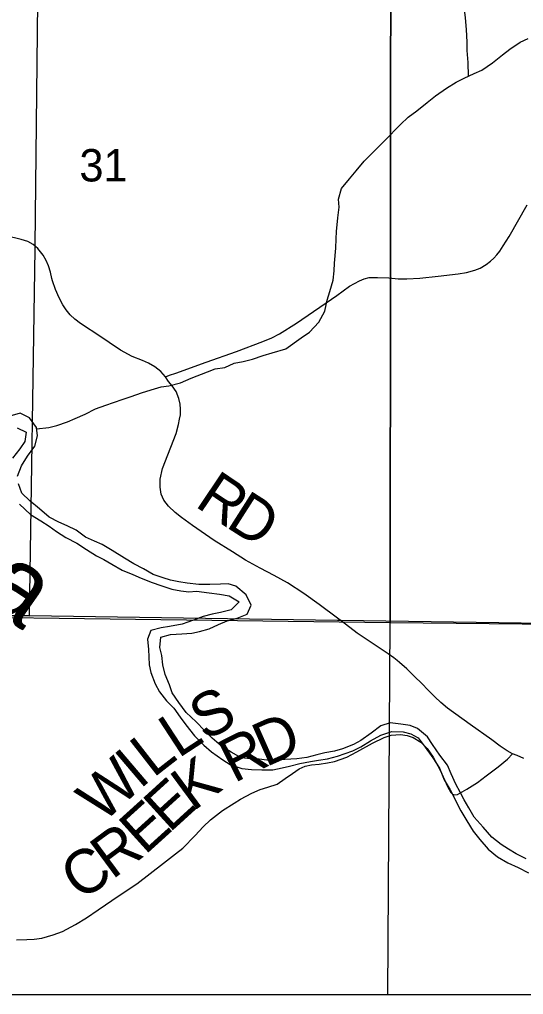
# Model space of a CAD drawing. Extents: x 0 to 191, y 0 to 55.
# Drawn here: x 184.796 to 185.447, y 47.92 to 49.18 of the extents above; entities that cross this region are included whole.
import ezdxf

# ---------------------------------------------------------------- set-up
doc = ezdxf.new("R2010")
doc.units = 0
for name, color, linetype in [('GM_X_Corporation', 7, 'Continuous'), ('GM_X_County_Road', 7, 'Continuous'), ('GM_X_County_Road_Text', 7, 'Continuous'), ('GM_X_Minor_River', 7, 'Continuous'), ('GM_X_Minor_River_Text', 7, 'Continuous'), ('GM_X_Section_Text', 7, 'Continuous'), ('GM_X_Township_Road', 7, 'Continuous')]:
    doc.layers.add(name, color=color, linetype=linetype)

msp = doc.modelspace()

# ---------------------------------------------------------------- linework, layer by layer
at = {"layer": 'GM_X_Corporation'}
for points in [[(184.1701, 53.923), (184.1701, 47.9197), (186.2932, 47.9197), (186.2941, 48.012), (186.2991, 48.3871), (186.4921, 48.3828), (187.098, 48.377), (187.7625, 48.3707), (187.7657, 48.3707), (188.3304, 48.3653), (188.401, 48.3646), (188.9117, 48.3542), (189.3607, 48.345), (189.6849, 48.3383), (190.1514, 48.3336), (190.3574, 48.3286), (190.3641, 48.8031), (190.3751, 50.4761)], [(184.1701, 53.923), (184.1701, 49.9388), (184.171, 49.9388), (184.1826, 49.9387), (184.1847, 49.9387), (184.3733, 49.937), (184.3701, 49.6407), (184.3701, 49.6374), (184.3608, 48.4162), (184.8085, 48.4088), (184.8161, 48.8829), (184.8161, 48.8869), (184.8319, 50.3441), (184.8319, 50.3472), (184.8438, 50.7018)], [(190.3751, 50.4761), (190.3641, 48.8031), (190.3574, 48.3286), (190.1514, 48.3336), (189.6849, 48.3383), (189.3607, 48.345), (188.9117, 48.3542), (188.401, 48.3646), (188.3304, 48.3653), (187.7657, 48.3707), (187.7625, 48.3707), (187.098, 48.377), (186.4921, 48.3828), (186.2991, 48.3871), (186.1484, 48.3893), (186.1442, 48.3893), (185.2112, 48.4029), (185.207, 48.403), (184.8085, 48.4088), (184.8161, 48.8829), (184.8161, 48.8869), (184.8319, 50.3441), (184.8319, 50.3472), (184.8438, 50.7018)]]:
    msp.add_lwpolyline(points, dxfattribs=at)
for points in [[(184.3647, 49.4297), (185.276, 49.4114), (185.2748, 48.3999), (184.3526, 48.412), (184.3573, 48.9248)], [(185.276, 49.4114), (186.3119, 49.3947), (186.3, 48.3895), (185.2748, 48.3999)], [(184.3521, 47.9197), (185.2718, 47.9197), (185.2748, 48.3999), (184.3526, 48.412), (184.3521, 47.9349)], [(184.357, 47.9197), (186.2932, 47.9197), (186.2941, 48.012), (186.2991, 48.3871), (186.1484, 48.3893), (186.1442, 48.3893), (185.2112, 48.4029), (185.207, 48.403), (184.8085, 48.4088), (184.3608, 48.4162)]]:
    msp.add_lwpolyline(points, close=True, dxfattribs=at)
at = {"layer": 'GM_X_County_Road'}
for points in [[(184.8383, 48.8419), (184.8374, 48.8447), (184.8356, 48.8529), (184.833, 48.8614), (184.8302, 48.868), (184.8265, 48.8749), (184.8194, 48.8836), (184.8163, 48.8864), (184.8136, 48.8889), (184.8067, 48.8928), (184.7978, 48.8952), (184.7783, 48.9001)], [(185.2839, 48.3514), (185.2798, 48.3548), (185.2723, 48.36), (185.2543, 48.3719), (185.2323, 48.3867), (185.2114, 48.4024), (185.2067, 48.4059), (185.1833, 48.4238), (185.1633, 48.438), (185.1423, 48.4517), (185.1252, 48.4613), (185.1071, 48.4704), (185.0881, 48.481), (185.0712, 48.4915), (185.0476, 48.5064), (185.0194, 48.5257), (185.0053, 48.5359), (184.9971, 48.5426), (184.9883, 48.5505), (184.9825, 48.5583), (184.979, 48.5663), (184.9777, 48.5753), (184.9777, 48.5856), (184.9807, 48.5995), (184.9981, 48.6446), (185.0014, 48.6563), (185.0028, 48.6632), (185.004, 48.6688), (185.004, 48.6762), (185.0035, 48.6827), (185.0017, 48.6898), (184.9981, 48.6987), (184.9929, 48.7062), (184.9883, 48.712), (184.9843, 48.7179), (184.9783, 48.7246), (184.9709, 48.7309), (184.9624, 48.7355), (184.9547, 48.7388), (184.9414, 48.7443), (184.9263, 48.7525), (184.9115, 48.7624), (184.9009, 48.7697), (184.8746, 48.7867), (184.8671, 48.7923), (184.8613, 48.7978), (184.856, 48.8045), (184.8517, 48.8109), (184.8468, 48.8201), (184.8421, 48.8308), (184.8383, 48.8419)], [(185.4331, 48.2306), (185.4261, 48.2345), (185.4171, 48.2406), (185.4065, 48.2488), (185.3786, 48.2687), (185.3491, 48.2898), (185.3406, 48.2968), (185.3328, 48.3043), (185.324, 48.3131), (185.3158, 48.3214), (185.3063, 48.3305), (185.2964, 48.3404), (185.2871, 48.3488), (185.2839, 48.3514)], [(184.7918, 47.9903), (184.8054, 47.9906), (184.8145, 47.9914), (184.8244, 47.9923), (184.8392, 47.9967), (184.8514, 48.0012), (184.8683, 48.0102), (184.8824, 48.0189), (184.8973, 48.029), (184.9247, 48.0475), (184.9474, 48.0626), (184.982, 48.0893), (184.9976, 48.1013), (185.0071, 48.1089), (185.023, 48.1253), (185.0331, 48.1362), (185.0428, 48.1452), (185.058, 48.1576), (185.0734, 48.167), (185.0816, 48.1721), (185.0961, 48.18), (185.1071, 48.1846), (185.1169, 48.1877), (185.129, 48.1917), (185.1391, 48.1986), (185.1486, 48.2051), (185.1575, 48.2111), (185.1651, 48.2148), (185.1732, 48.2164), (185.1831, 48.2172), (185.1938, 48.2189), (185.2032, 48.2208), (185.2188, 48.2264), (185.2318, 48.2331), (185.2522, 48.2444), (185.267, 48.2517), (185.2761, 48.2548), (185.2883, 48.2558), (185.297, 48.2544), (185.3048, 48.2518), (185.3148, 48.2457), (185.3226, 48.2377), (185.3305, 48.2265), (185.3398, 48.2094), (185.3497, 48.1874), (185.3535, 48.1806), (185.3555, 48.1787), (185.3584, 48.1775), (185.3621, 48.1783), (185.3741, 48.1849), (185.3877, 48.1936), (185.3993, 48.2023), (185.4144, 48.2141), (185.4265, 48.2239), (185.4331, 48.2306)], [(185.4477, 48.2245), (185.4393, 48.2286), (185.4331, 48.2306)]]:
    msp.add_lwpolyline(points, dxfattribs=at)
at = {"layer": 'GM_X_Minor_River'}
for points in [[(185.3764, 49.1063), (185.376, 49.124), (185.3744, 49.1395), (185.3744, 49.1505), (185.3736, 49.1668), (185.3724, 49.1816), (185.3709, 49.1923), (185.3701, 49.2033), (185.367, 49.2128), (185.3625, 49.2256), (185.3548, 49.2408), (185.3487, 49.2537), (185.3426, 49.2673), (185.3377, 49.2817), (185.3335, 49.2946), (185.3323, 49.3091), (185.3322, 49.3326), (185.333, 49.344), (185.3341, 49.3539), (185.3337, 49.3645), (185.331, 49.377), (185.3283, 49.3891)], [(185.14, 48.7542), (185.1597, 48.7683), (185.1707, 48.7756), (185.1828, 48.7885), (185.1904, 48.8026), (185.1934, 48.817), (185.1968, 48.8281), (185.2013, 48.8429), (185.2024, 48.8546), (185.2031, 48.8649), (185.2046, 48.8839), (185.205, 48.896), (185.2057, 48.9055), (185.2072, 48.9234), (185.209, 48.937), (185.2083, 48.9473), (185.212, 48.961), (185.2226, 48.9739), (185.2309, 48.9842), (185.2415, 48.9964), (185.2552, 49.0101), (185.268, 49.0234), (185.2885, 49.044), (185.2983, 49.0535), (185.3093, 49.0615), (185.3226, 49.0722), (185.3336, 49.0809), (185.3476, 49.0908), (185.3605, 49.0985), (185.3707, 49.1038), (185.3836, 49.1096), (185.3934, 49.1141), (185.4071, 49.1237), (185.42, 49.134), (185.4298, 49.1412), (185.4431, 49.1504), (185.4533, 49.155)], [(184.8179, 48.6507), (184.8336, 48.6523), (184.8442, 48.6551), (184.8578, 48.6597), (184.8676, 48.6639), (184.8805, 48.6697), (184.894, 48.6766), (184.9073, 48.6812), (184.9171, 48.6847), (184.9299, 48.6889), (184.9401, 48.6924), (184.9533, 48.697), (184.9658, 48.7009), (184.979, 48.7048), (184.9889, 48.7064), (185.004, 48.7099), (185.0176, 48.716), (185.0387, 48.7245), (185.0486, 48.728), (185.061, 48.7299), (185.0731, 48.7357), (185.0848, 48.7376), (185.0969, 48.7408), (185.1109, 48.7454), (185.1226, 48.7489), (185.14, 48.7542)], [(184.7931, 48.5895), (184.7983, 48.6028), (184.8062, 48.6154), (184.8156, 48.6283), (184.8189, 48.6416), (184.8177, 48.6522), (184.8086, 48.6647), (184.7964, 48.6711), (184.7832, 48.6668)], [(184.7927, 48.6521), (184.8045, 48.6465), (184.8027, 48.6343), (184.7963, 48.6248), (184.7865, 48.6126)], [(185.2504, 48.2573), (185.2372, 48.2481), (185.2274, 48.2427), (185.2134, 48.2373), (185.2028, 48.2342), (185.1903, 48.2319), (185.1801, 48.2295), (185.1673, 48.226), (185.1544, 48.2244), (185.1389, 48.2232), (185.1253, 48.2224), (185.1154, 48.2227), (185.1056, 48.2238), (185.095, 48.2241), (185.0825, 48.2255), (185.0692, 48.2327), (185.0567, 48.2406), (185.0449, 48.2511), (185.035, 48.2609), (185.0243, 48.2722), (185.0114, 48.2843), (185.0018, 48.2971), (184.9931, 48.3096), (184.9896, 48.3198), (184.9842, 48.3331), (184.9811, 48.3459), (184.9799, 48.3577), (184.9772, 48.3679), (184.9783, 48.3816), (184.9911, 48.3847), (185.0055, 48.3859), (185.0187, 48.3868), (185.0286, 48.3887), (185.041, 48.3922), (185.0531, 48.3976), (185.0641, 48.4026), (185.0773, 48.4061), (185.0901, 48.4111), (185.0954, 48.4229), (185.0888, 48.4361), (185.0755, 48.4474), (185.0657, 48.4504), (185.0558, 48.4499), (185.0418, 48.4495), (185.0275, 48.4494), (185.0127, 48.4512), (185.0017, 48.453), (184.9911, 48.4553), (184.9816, 48.4579), (184.9687, 48.4623), (184.9562, 48.4698), (184.9436, 48.4762), (184.9315, 48.4834), (184.9155, 48.4935), (184.9026, 48.501), (184.8928, 48.5055), (184.881, 48.5107), (184.8688, 48.5198), (184.8574, 48.5254), (184.8464, 48.5299), (184.8339, 48.5366), (184.8217, 48.5472), (184.8092, 48.5574), (184.7989, 48.5675), (184.7943, 48.5797)], [(184.7956, 48.5535), (184.8101, 48.5399), (184.8233, 48.5316), (184.834, 48.5249), (184.8435, 48.5181), (184.8556, 48.5102), (184.8697, 48.5031), (184.8822, 48.4948), (184.8951, 48.4866), (184.9046, 48.4817), (184.9149, 48.4757), (184.9286, 48.4682), (184.9422, 48.4622), (184.9532, 48.4577), (184.9673, 48.4521), (184.9783, 48.4484), (184.9927, 48.4435), (185.0044, 48.4413), (185.0146, 48.4402), (185.0245, 48.4407), (185.0411, 48.4389), (185.0544, 48.437), (185.0669, 48.4348), (185.0798, 48.4269), (185.0693, 48.4166), (185.0557, 48.4135), (185.0447, 48.4112), (185.033, 48.4081), (185.0209, 48.4035), (185.0062, 48.3981), (184.9895, 48.3953), (184.9789, 48.3937), (184.9657, 48.3899), (184.9612, 48.3788), (184.9625, 48.3656), (184.9629, 48.3561), (184.9633, 48.3458), (184.9657, 48.3356), (184.971, 48.3212), (184.9768, 48.311), (184.9859, 48.2993), (184.9951, 48.2895), (185.0035, 48.2782), (185.0107, 48.268), (185.0218, 48.254), (185.034, 48.2419), (185.0438, 48.2333), (185.0587, 48.2231), (185.0682, 48.2171), (185.083, 48.2119), (185.0955, 48.2104), (185.1091, 48.2098), (185.1231, 48.2098), (185.1352, 48.2126), (185.145, 48.2149), (185.1582, 48.218), (185.1718, 48.2208), (185.1821, 48.2223), (185.1938, 48.2243), (185.207, 48.2278), (185.2168, 48.2313), (185.2266, 48.2344), (185.2372, 48.2397)], [(185.4508, 48.095), (185.4379, 48.1013), (185.428, 48.1077), (185.4185, 48.1137), (185.4063, 48.1231), (185.3953, 48.136), (185.3835, 48.1488), (185.3766, 48.1609), (185.3708, 48.1711), (185.3655, 48.1813), (185.3598, 48.1915), (185.354, 48.2048), (185.349, 48.2161), (185.3391, 48.229), (185.3296, 48.2426), (185.3231, 48.2528), (185.3105, 48.2633), (185.301, 48.2674), (185.2889, 48.2692), (185.2749, 48.2707), (185.2628, 48.2668), (185.2504, 48.2573)], [(185.2372, 48.2397), (185.2497, 48.2474), (185.2629, 48.2547), (185.2772, 48.2597), (185.2916, 48.259), (185.3015, 48.2564), (185.311, 48.2512), (185.3201, 48.2395), (185.33, 48.2255), (185.3388, 48.2123), (185.3446, 48.1971), (185.3526, 48.1843), (185.3664, 48.157), (185.374, 48.1442), (185.3824, 48.1306), (185.3908, 48.12), (185.4015, 48.1076), (185.4137, 48.0978), (185.427, 48.0899), (185.4406, 48.0839), (185.4539, 48.0768)]]:
    msp.add_lwpolyline(points, dxfattribs=at)
at = {"layer": 'GM_X_Township_Road'}
msp.add_lwpolyline([(184.9843, 48.7179), (184.9895, 48.7198), (184.9978, 48.7225), (185.0371, 48.7366), (185.0764, 48.7506), (185.1104, 48.7636), (185.1219, 48.7681), (185.1319, 48.7734), (185.1537, 48.7872), (185.2062, 48.8231), (185.2225, 48.8352), (185.2353, 48.8421), (185.2415, 48.8444), (185.2477, 48.846), (185.2586, 48.8464), (185.2734, 48.8456), (185.2851, 48.8446), (185.2964, 48.8445), (185.3133, 48.8454), (185.337, 48.8481), (185.3628, 48.8508), (185.3735, 48.8528), (185.3843, 48.8558), (185.3912, 48.8584), (185.3993, 48.8631), (185.4046, 48.8672), (185.4088, 48.871), (185.4127, 48.8754), (185.4167, 48.8802), (185.4212, 48.887), (185.4289, 48.899), (185.4522, 48.9401)], dxfattribs=at)

# ---------------------------------------------------------------- texts
at = {"layer": 'GM_X_County_Road_Text'}
for s, rotation, p in [('R', 326.2125, (185.021, 48.5515)), ('D', 327.4779, (185.0609, 48.5248)), ('S', 27.7466, (185.0353, 48.2467)), ('L', 33.1516, (185.001, 48.2242)), ('D', 23.9625, (185.1139, 48.2131)), ('R', 27.0503, (185.0731, 48.1922)), ('L', 37.9336, (184.9685, 48.1988)), ('W', 42.8045, (184.9034, 48.1398)), ('I', 40.3972, (184.9512, 48.1841)), ('K', 36.4211, (185.0197, 48.1553)), ('E', 42.3283, (184.9894, 48.1277)), ('E', 42.1118, (184.9577, 48.099)), ('R', 36.4297, (184.9154, 48.0674)), ('C', 33.5082, (184.8739, 48.0398))]:
    msp.add_text(s, height=0.0568, rotation=rotation, dxfattribs=at).set_placement(p)
at = {"layer": 'GM_X_Minor_River_Text'}
msp.add_text('Seneca', height=0.09469, rotation=325.0067, dxfattribs=at).set_placement((184.4482, 48.6362))
at = {"layer": 'GM_X_Section_Text'}
msp.add_text('31', height=0.04186, rotation=0, dxfattribs=at).set_placement((184.8732, 48.9703))

doc.saveas('drawing.dxf')
